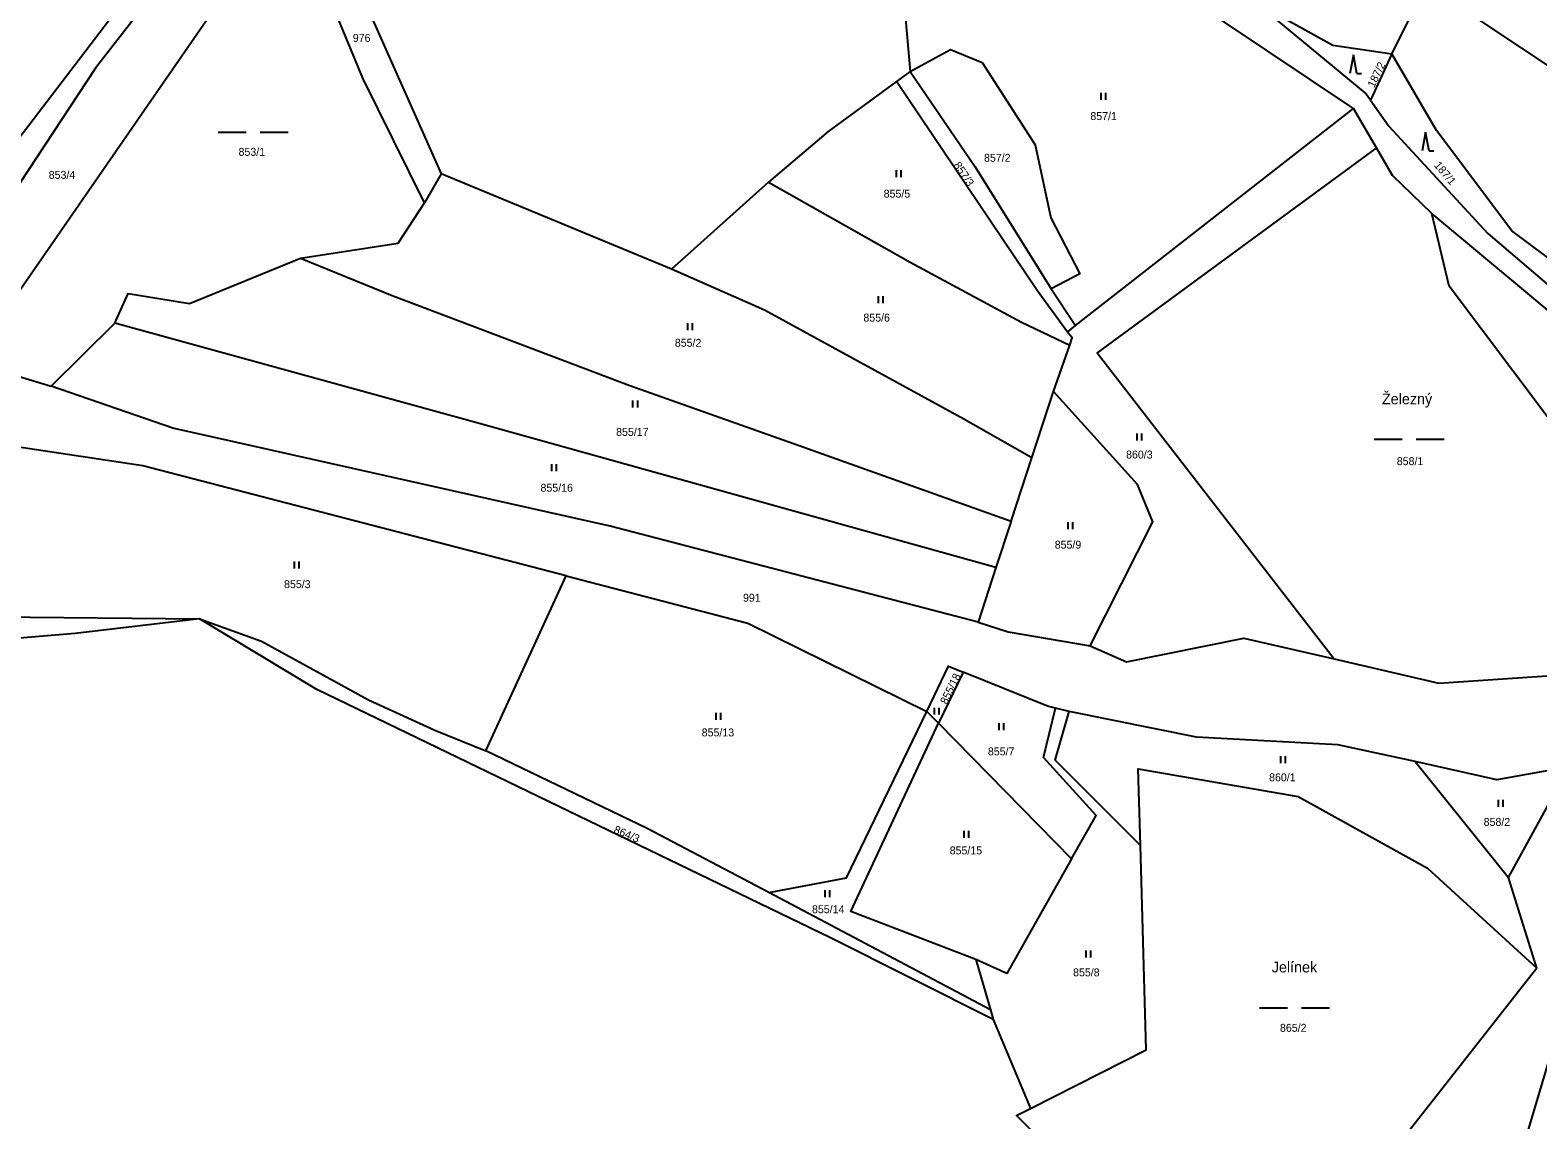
# Model space of a CAD drawing. Extents: x -751333 to -746055, y -1133395 to -1129777.
# Drawn here: x -747546.5 to -747223.3, y -1131865 to -1131631.4 of the extents above; entities that cross this region are included whole.
import ezdxf

# ---------------------------------------------------------------- set-up
doc = ezdxf.new("R2010")
doc.units = 0
for name, color, linetype in [('Hranice parcel', 7, 'Continuous'), ('Parcelní čísla', 7, 'Continuous'), ('Pop  PČ popisy', 7, 'Continuous'), ('Značky kultur', 7, 'Continuous')]:
    doc.layers.add(name, color=color, linetype=linetype)

msp = doc.modelspace()

# ---------------------------------------------------------------- linework, layer by layer
at = {"layer": 'Hranice parcel'}
for p, q in [((-747361.08, -1131602.88), (-747357.88, -1131640.25)), ((-747478.47, -1131617.02), (-747458.45, -1131662.17)), ((-747254.6, -1131636.41), (-747247.17, -1131621.56)), ((-747254.6, -1131636.41), (-747259.18, -1131646.33)), ((-747357.88, -1131640.25), (-747360.8, -1131642.37)), ((-747322.41, -1131694.68), (-747262.86, -1131648.18)), ((-747257.91, -1131656.57), (-747262.86, -1131648.18)), ((-747458.45, -1131662.17), (-747462.01, -1131668.39)), ((-747409.06, -1131682.61), (-747458.45, -1131662.17)), ((-747388.27, -1131663.97), (-747409.06, -1131682.61)), ((-747327.68, -1131686.79), (-747322.41, -1131694.68)), ((-747542.02, -1131707.68), (-747528.4, -1131694.14)), ((-747324.17, -1131696.09), (-747322.41, -1131694.68)), ((-747327.11, -1131708.86), (-747323.64, -1131698.92)), ((-747559.41, -1131702.48), (-747542.02, -1131707.68)), ((-747331.81, -1131723.04), (-747327.11, -1131708.86)), ((-747336.24, -1131736.62), (-747331.81, -1131723.04)), ((-747336.24, -1131736.62), (-747339.49, -1131746.59)), ((-747339.49, -1131746.59), (-747343.31, -1131758.31)), ((-747448.86, -1131785.87), (-747431.62, -1131748.34)), ((-747555.53, -1131757.15), (-747510.21, -1131757.54)), ((-747346.48, -1131768.98), (-747351.83, -1131779.93)), ((-747323.8, -1131777.42), (-747326.7, -1131776.72)), ((-747351.83, -1131779.93), (-747354.27, -1131777.45)), ((-747351.83, -1131779.93), (-747323.26, -1131809)), ((-747249.62, -1131788.14), (-747229.61, -1131813)), ((-747229.61, -1131813), (-747216.62, -1131789.31)), ((-747223.51, -1131832.44), (-747229.61, -1131813)), ((-747340.66, -1131841.38), (-747388.18, -1131816.27)), ((-747343.77, -1131830.6), (-747340.66, -1131841.38)), ((-747223.51, -1131832.44), (-747265.2, -1131885.54)), ((-747340.66, -1131841.38), (-747340.05, -1131843.48)), ((-747340.05, -1131843.48), (-747332.1, -1131862.53))]:
    msp.add_line(p, q, dxfattribs=at)
for points in [[(-747443.45, -1131514.26), (-747480.55, -1131563.87), (-747518.42, -1131614.59), (-747550, -1131656.02), (-747584.22, -1131698.64)], [(-747462.01, -1131668.39), (-747475.19, -1131641.65), (-747484.66, -1131618.77), (-747495.81, -1131591.02)], [(-747262.86, -1131648.18), (-747290.52, -1131629.64), (-747320.83, -1131612.14), (-747361.08, -1131602.88)], [(-747512.18, -1131613.29), (-747532.53, -1131639.52), (-747561.47, -1131683.37), (-747579.28, -1131700.12)], [(-747512.18, -1131613.29), (-747502.43, -1131618.94), (-747504.69, -1131623.44), (-747559.41, -1131702.48)], [(-747129.15, -1131700.25), (-747185.86, -1131662.35), (-747247.17, -1131621.56)], [(-747283.76, -1131625.43), (-747267.27, -1131634.55), (-747254.6, -1131636.41)], [(-747259.18, -1131646.33), (-747260.33, -1131644.82), (-747283.76, -1131625.43)], [(-747357.88, -1131640.25), (-747349.2, -1131635.5), (-747342.45, -1131638.32), (-747331.11, -1131655.97), (-747327.7, -1131671.61), (-747321.53, -1131683.62), (-747327.68, -1131686.79)], [(-747172.52, -1131716.41), (-747228.87, -1131674.36), (-747245.07, -1131652.89), (-747254.6, -1131636.41)], [(-747357.88, -1131640.25), (-747343.93, -1131660.68), (-747327.68, -1131686.79)], [(-747360.8, -1131642.37), (-747375.43, -1131653.05), (-747388.27, -1131663.97)], [(-747324.17, -1131696.09), (-747330.67, -1131687.18), (-747360.8, -1131642.37)], [(-747259.18, -1131646.33), (-747255.29, -1131651.97), (-747234.06, -1131674.93), (-747201.42, -1131702.74), (-747172.52, -1131716.41)], [(-747257.91, -1131656.57), (-747317.79, -1131700.5), (-747267.01, -1131766.16)], [(-747246.06, -1131670.63), (-747254.48, -1131662.48), (-747257.91, -1131656.57)], [(-747388.27, -1131663.97), (-747357.85, -1131681.06), (-747334, -1131693.97), (-747323.64, -1131698.92)], [(-747488.58, -1131680.22), (-747467.61, -1131677.03), (-747462.01, -1131668.39)], [(-747194.42, -1131749.94), (-747242.32, -1131686.21), (-747246.06, -1131670.63)], [(-747143.51, -1131733.86), (-747163.2, -1131726.49), (-747177.09, -1131722.8), (-747200.93, -1131708.24), (-747246.06, -1131670.63)], [(-747528.4, -1131694.14), (-747525.49, -1131687.82), (-747512.4, -1131689.95), (-747488.58, -1131680.22)], [(-747488.58, -1131680.22), (-747468.94, -1131688.21), (-747417.95, -1131707.56), (-747381.64, -1131720.38), (-747336.24, -1131736.62)], [(-747331.81, -1131723.04), (-747346.34, -1131714.79), (-747389.09, -1131691.38), (-747409.06, -1131682.61)], [(-747339.49, -1131746.59), (-747451.3, -1131715.37), (-747528.4, -1131694.14)], [(-747323.64, -1131698.92), (-747323.11, -1131697.35), (-747324.17, -1131696.09)], [(-747343.31, -1131758.31), (-747422.18, -1131737.69), (-747515.95, -1131716.72), (-747542.02, -1131707.68)], [(-747319.28, -1131763.36), (-747305.82, -1131736.8), (-747309.11, -1131728.78), (-747327.11, -1131708.86)], [(-747431.62, -1131748.34), (-747522.4, -1131724.74), (-747551.8, -1131720.33)], [(-747431.62, -1131748.34), (-747392.64, -1131758.47), (-747354.27, -1131777.45)], [(-747510.21, -1131757.54), (-747536.87, -1131760.7), (-747601, -1131766.04)], [(-747510.21, -1131757.54), (-747496.95, -1131762.32), (-747474.01, -1131774.9), (-747459.79, -1131781.43), (-747448.86, -1131785.87)], [(-747340.05, -1131843.48), (-747375.12, -1131825.91), (-747485.07, -1131772.73), (-747510.21, -1131757.54)], [(-747343.31, -1131758.31), (-747336.85, -1131760.37), (-747319.28, -1131763.36)], [(-747319.28, -1131763.36), (-747311.5, -1131766.78), (-747286.37, -1131761.74), (-747267.01, -1131766.16)], [(-747267.01, -1131766.16), (-747244.55, -1131771.35), (-747202.38, -1131768.48)], [(-747354.27, -1131777.45), (-747349.64, -1131767.7), (-747346.48, -1131768.98)], [(-747326.7, -1131776.72), (-747328.4, -1131776.31), (-747346.48, -1131768.98)], [(-747323.26, -1131809), (-747318.03, -1131799.74), (-747329.29, -1131787.29), (-747326.7, -1131776.72)], [(-747388.18, -1131816.27), (-747371.51, -1131813.1), (-747354.27, -1131777.45)], [(-747343.77, -1131830.6), (-747370.56, -1131820.28), (-747351.83, -1131779.93)], [(-747308.51, -1131806.18), (-747326.78, -1131787.84), (-747323.8, -1131777.42)], [(-747249.62, -1131788.14), (-747266.19, -1131784.57), (-747296.48, -1131782.93), (-747323.8, -1131777.42)], [(-747388.18, -1131816.27), (-747414.25, -1131802.49), (-747448.86, -1131785.87)], [(-747308.51, -1131806.18), (-747308.97, -1131789.7), (-747274.72, -1131795.65), (-747246.96, -1131810.99), (-747223.51, -1131832.44)], [(-747216.62, -1131789.31), (-747232.12, -1131792.08), (-747249.62, -1131788.14)], [(-747224.99, -1131886.58), (-747230.08, -1131883.19), (-747216.68, -1131837.99), (-747213.89, -1131810.39), (-747211.65, -1131788.43)], [(-747332.1, -1131862.53), (-747307.27, -1131850), (-747308.51, -1131806.18)], [(-747323.26, -1131809), (-747337.16, -1131833.58), (-747343.77, -1131830.6)], [(-747316.12, -1131882.74), (-747335.11, -1131864.05), (-747332.1, -1131862.53)]]:
    msp.add_lwpolyline(points, dxfattribs=at)
at = {"layer": 'Značky kultur'}
for p, q in [((-747262.84, -1131636.62), (-747263.59, -1131640.62)), ((-747262.09, -1131640.62), (-747262.84, -1131636.62)), ((-747262.09, -1131640.62), (-747261.094, -1131640.62)), ((-747316.931, -1131646.32), (-747316.931, -1131644.82)), ((-747315.93, -1131646.32), (-747315.93, -1131644.82)), ((-747506.239, -1131653.22), (-747500.239, -1131653.22)), ((-747497.239, -1131653.22), (-747491.239, -1131653.22)), ((-747247.38, -1131653.21), (-747248.13, -1131657.21)), ((-747246.63, -1131657.21), (-747247.38, -1131653.21)), ((-747246.63, -1131657.21), (-747245.634, -1131657.21)), ((-747360.821, -1131662.85), (-747360.821, -1131661.35)), ((-747359.82, -1131662.85), (-747359.82, -1131661.35)), ((-747364.681, -1131689.9), (-747364.681, -1131688.4)), ((-747363.68, -1131689.9), (-747363.68, -1131688.4)), ((-747405.531, -1131695.68), (-747405.531, -1131694.18)), ((-747404.53, -1131695.68), (-747404.53, -1131694.18)), ((-747417.291, -1131712.27), (-747417.291, -1131710.77)), ((-747416.29, -1131712.27), (-747416.29, -1131710.77)), ((-747309.191, -1131719.3), (-747309.191, -1131717.8)), ((-747308.19, -1131719.3), (-747308.19, -1131717.8)), ((-747258.389, -1131719.04), (-747252.389, -1131719.04)), ((-747249.389, -1131719.04), (-747243.389, -1131719.04)), ((-747434.671, -1131725.89), (-747434.671, -1131724.39)), ((-747433.67, -1131725.89), (-747433.67, -1131724.39)), ((-747324.011, -1131738.34), (-747324.011, -1131736.84)), ((-747323.01, -1131738.34), (-747323.01, -1131736.84)), ((-747489.851, -1131746.77), (-747489.851, -1131745.27)), ((-747488.85, -1131746.77), (-747488.85, -1131745.27)), ((-747352.681, -1131778.11), (-747352.681, -1131776.61)), ((-747351.68, -1131778.11), (-747351.68, -1131776.61)), ((-747399.461, -1131779.22), (-747399.461, -1131777.72)), ((-747398.46, -1131779.22), (-747398.46, -1131777.72)), ((-747338.811, -1131781.46), (-747338.811, -1131779.96)), ((-747337.81, -1131781.46), (-747337.81, -1131779.96)), ((-747278.381, -1131788.52), (-747278.381, -1131787.02)), ((-747277.38, -1131788.52), (-747277.38, -1131787.02)), ((-747231.751, -1131797.89), (-747231.751, -1131796.39)), ((-747230.75, -1131797.89), (-747230.75, -1131796.39)), ((-747346.331, -1131804.52), (-747346.331, -1131803.02)), ((-747345.33, -1131804.52), (-747345.33, -1131803.02)), ((-747376.071, -1131817.22), (-747376.071, -1131815.72)), ((-747375.07, -1131817.22), (-747375.07, -1131815.72)), ((-747320.171, -1131830.16), (-747320.171, -1131828.66)), ((-747319.17, -1131830.16), (-747319.17, -1131828.66)), ((-747282.949, -1131841), (-747276.949, -1131841)), ((-747273.949, -1131841), (-747267.949, -1131841))]:
    msp.add_line(p, q, dxfattribs=at)

# ---------------------------------------------------------------- texts
at = {"layer": 'Parcelní čísla'}
for s, p in [('976', (-747477.36, -1131633.87)), ('857/1', (-747319.24, -1131650.63)), ('853/1', (-747501.85, -1131658.3)), ('857/2', (-747342.04, -1131659.57)), ('853/4', (-747542.55, -1131663.23)), ('855/5', (-747363.55, -1131667.26)), ('855/6', (-747367.9, -1131693.84)), ('855/2', (-747408.32, -1131699.23)), ('855/17', (-747420.91, -1131718.34)), ('860/3', (-747311.58, -1131723.19)), ('858/1', (-747253.55, -1131724.61)), ('855/16', (-747437.12, -1131730.31)), ('855/9', (-747326.88, -1131742.51)), ('855/3', (-747492.1, -1131750.98)), ('991', (-747393.71, -1131753.89)), ('855/13', (-747402.56, -1131782.77)), ('855/7', (-747341.21, -1131786.84)), ('860/1', (-747280.93, -1131792.4)), ('858/2', (-747234.93, -1131801.95)), ('855/15', (-747349.4, -1131808.07)), ('855/14', (-747378.92, -1131820.68)), ('855/8', (-747322.95, -1131834.21)), ('865/2', (-747278.59, -1131846.1))]:
    msp.add_text(s, height=1.7, dxfattribs=at).set_placement(p)
for s, rotation, p in [('187/2', 64, (-747258.406, -1131643.812)), ('857/3', 304, (-747348.634, -1131660.305)), ('187/1', 310, (-747245.661, -1131660.376)), ('855/18', 64, (-747350.006, -1131776.032)), ('864/3', 337, (-747421.572, -1131803.382))]:
    msp.add_text(s, height=1.7, rotation=rotation, dxfattribs=at).set_placement(p)
at = {"layer": 'Pop  PČ popisy'}
for s, p in [('Železný ', (-747256.73, -1131711.57)), ('Jelínek', (-747280.355, -1131833.37))]:
    msp.add_text(s, height=2.3, dxfattribs=at).set_placement(p)

doc.saveas('drawing.dxf')
